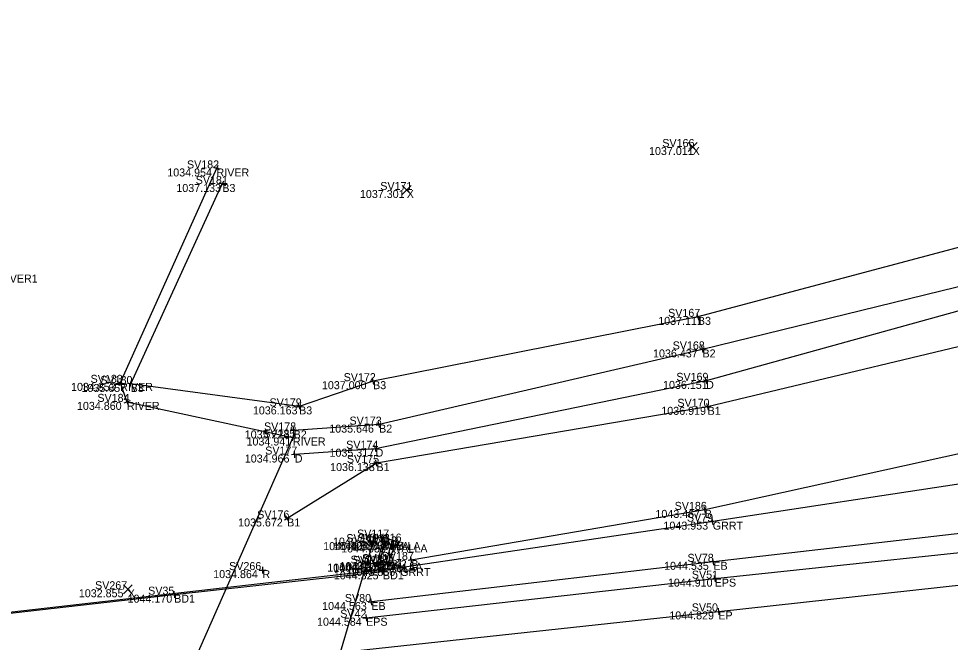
# Model space of a CAD drawing. Extents: x 1542529 to 1609210, y 587215 to 645373.
# Drawn here: x 1608930.2 to 1609069.9, y 645268.8 to 645362.2 of the extents above; entities that cross this region are included whole.
import ezdxf

# ---------------------------------------------------------------- set-up
doc = ezdxf.new("R2010")
doc.units = 0
for name, color, linetype in [('BR_X_SV_Abut', 7, 'Continuous'), ('BR_X_SV_Abut_Text', 7, 'Continuous'), ('BR_X_SV_Deck_Top', 7, 'Continuous'), ('BR_X_SV_Deck_Top_Text', 7, 'Continuous'), ('DR_X_Ditch', 7, 'Continuous'), ('HY_X_Water_Edge', 7, 'Continuous'), ('PV_X_EOP', 7, 'Continuous'), ('PV_X_Shoulder', 7, 'Continuous'), ('PV_X_Shoulder_Aggregate', 7, 'Continuous'), ('RD_X_GR_Rt', 7, 'Continuous'), ('SV_X_Break_Lines', 7, 'Continuous'), ('SV_X_Random_Point', 7, 'Continuous'), ('SV_X_Shot_Marker', 7, 'Continuous'), ('SV_X_Text_Comment', 7, 'Continuous'), ('SV_X_Text_Elevation', 7, 'Continuous'), ('SV_X_Text_Name', 7, 'Continuous'), ('SV_X_Toe_of_Slope', 7, 'Continuous'), ('SV_X_Top_of_Bank', 7, 'Continuous')]:
    doc.layers.add(name, color=color, linetype=linetype)

msp = doc.modelspace()

# ---------------------------------------------------------------- linework, layer by layer
at = {"layer": 'BR_X_SV_Abut'}
for points in [[(1608983.32, 645283.77), (1608967.84, 645231.45)], [(1608985.3, 645280.69), (1608986.07, 645283.42), (1608985.01, 645283.78), (1608984.29, 645280.5)]]:
    msp.add_lwpolyline(points, dxfattribs=at)
at = {"layer": 'BR_X_SV_Abut_Text'}
for p, q in [((1608983.8, 645283.63), (1608982.84, 645283.91)), ((1608983.46, 645284.25), (1608983.18, 645283.29)), ((1608983.32, 645283.77), (1608983.32, 645283.77)), ((1608985.48, 645283.61), (1608984.54, 645283.94)), ((1608984.85, 645283.3), (1608985.17, 645284.25)), ((1608985.01, 645283.78), (1608985.01, 645283.78)), ((1608985.93, 645282.93), (1608986.2, 645283.9)), ((1608985.58, 645283.55), (1608986.55, 645283.28)), ((1608986.07, 645283.42), (1608986.07, 645283.42)), ((1608984.4, 645280.99), (1608984.18, 645280.01)), ((1608984.82, 645280.82), (1608985.78, 645280.55)), ((1608985.17, 645280.21), (1608985.44, 645281.17)), ((1608984.78, 645280.39), (1608983.8, 645280.6)), ((1608984.29, 645280.5), (1608984.29, 645280.5)), ((1608985.3, 645280.69), (1608985.3, 645280.69))]:
    msp.add_line(p, q, dxfattribs=at)
at = {"layer": 'BR_X_SV_Deck_Top'}
msp.add_lwpolyline([(1608890.83, 645268.82), (1608915.28, 645271.59), (1608953.53, 645275.9), (1608984.83, 645279.39)], dxfattribs=at)
at = {"layer": 'BR_X_SV_Deck_Top_Text'}
for p, q in [((1608984.33, 645279.34), (1608985.32, 645279.45)), ((1608984.77, 645279.89), (1608984.88, 645278.9)), ((1608984.83, 645279.39), (1608984.83, 645279.39)), ((1608953.03, 645275.85), (1608954.02, 645275.96)), ((1608953.47, 645276.4), (1608953.58, 645275.4)), ((1608953.53, 645275.9), (1608953.53, 645275.9))]:
    msp.add_line(p, q, dxfattribs=at)
at = {"layer": 'DR_X_Ditch'}
msp.add_lwpolyline([(1609191.48, 645350.17), (1609137.17, 645337.41), (1609083.09, 645321.71), (1609033.27, 645307.94), (1608983.73, 645297.77), (1608971.61, 645296.9)], dxfattribs=at)
at = {"layer": 'HY_X_Water_Edge'}
msp.add_lwpolyline([(1608959.88, 645339.77), (1608945.44, 645307.64), (1608946.45, 645304.79), (1608971.33, 645299.45), (1608940.9, 645230.56)], dxfattribs=at)
at = {"layer": 'PV_X_EOP'}
msp.add_lwpolyline([(1608980.54, 645267.46), (1609035.11, 645273.39), (1609089.32, 645279.34), (1609143.54, 645285.01), (1609196.2, 645290.63)], dxfattribs=at)
at = {"layer": 'PV_X_Shoulder'}
msp.add_lwpolyline([(1608982.3, 645272.44), (1609034.56, 645278.3), (1609089.21, 645284.1), (1609142.99, 645289.57), (1609196.38, 645295.25)], dxfattribs=at)
at = {"layer": 'PV_X_Shoulder_Aggregate'}
msp.add_lwpolyline([(1609194.27, 645298.83), (1609142.65, 645292.29), (1609089.13, 645287.12), (1609034.36, 645280.82), (1608983.09, 645274.8)], dxfattribs=at)
at = {"layer": 'RD_X_GR_Rt'}
for p, q in [((1609087.09, 645294.87), (1609034.27, 645286.84)), ((1609034.27, 645286.84), (1608987.41, 645279.9)), ((1608987.41, 645279.9), (1608890.95, 645268.94))]:
    msp.add_line(p, q, dxfattribs=at)
at = {"layer": 'SV_X_Break_Lines'}
msp.add_lwpolyline([(1608985.67, 645280.77), (1608986.85, 645283.85), (1608984.91, 645284.45), (1608983.95, 645280.55)], dxfattribs=at)
at = {"layer": 'SV_X_Random_Point'}
for p, q in [((1609030.58, 645342.32), (1609031.91, 645343.65)), ((1609030.58, 645343.65), (1609031.91, 645342.32)), ((1608987.73, 645335.87), (1608989.07, 645337.21)), ((1608987.73, 645337.21), (1608989.07, 645335.87)), ((1608945.92, 645276.04), (1608947.25, 645277.37)), ((1608945.92, 645277.37), (1608947.25, 645276.04))]:
    msp.add_line(p, q, dxfattribs=at)
at = {"layer": 'SV_X_Shot_Marker'}
for p, q in [((1608960.34, 645339.56), (1608959.43, 645339.97)), ((1608960.09, 645340.23), (1608959.68, 645339.31)), ((1608959.88, 645339.77), (1608959.88, 645339.77)), ((1608960.3, 645337.64), (1608961.21, 645337.23)), ((1608960.54, 645336.98), (1608960.96, 645337.89)), ((1608960.75, 645337.44), (1608960.75, 645337.44)), ((1609032.52, 645317.66), (1609031.56, 645317.4)), ((1609032.17, 645317.05), (1609031.91, 645318.01)), ((1609032.04, 645317.53), (1609032.04, 645317.53)), ((1609032.85, 645312.17), (1609032.61, 645313.14)), ((1609033.22, 645312.77), (1609032.25, 645312.54)), ((1609032.73, 645312.65), (1609032.73, 645312.65)), ((1608945.9, 645307.44), (1608944.98, 645307.85)), ((1608945.64, 645308.1), (1608945.23, 645307.19)), ((1608945.44, 645307.64), (1608945.44, 645307.64)), ((1608947.5, 645307.4), (1608946.51, 645307.53)), ((1608946.94, 645306.97), (1608947.07, 645307.96)), ((1608947.01, 645307.47), (1608947.01, 645307.47)), ((1608983.84, 645307.99), (1608982.86, 645307.79)), ((1608983.45, 645307.4), (1608983.25, 645308.38)), ((1608983.35, 645307.89), (1608983.35, 645307.89)), ((1609033.76, 645308.08), (1609032.79, 645307.81)), ((1609033.41, 645307.46), (1609033.14, 645308.42)), ((1609033.27, 645307.94), (1609033.27, 645307.94)), ((1608946.92, 645304.96), (1608945.98, 645304.62)), ((1608946.28, 645305.26), (1608946.62, 645304.32)), ((1608946.45, 645304.79), (1608946.45, 645304.79)), ((1608972.42, 645303.64), (1608972.1, 645304.59)), ((1609033.61, 645303.56), (1609033.38, 645304.53)), ((1608972.73, 645304.27), (1608971.78, 645303.95)), ((1608972.26, 645304.11), (1608972.26, 645304.11)), ((1609033.98, 645304.16), (1609033.01, 645303.93)), ((1609033.5, 645304.05), (1609033.5, 645304.05)), ((1608984.36, 645300.89), (1608984.13, 645301.87)), ((1608971.93, 645300.54), (1608970.94, 645300.47)), ((1608971.47, 645300.01), (1608971.4, 645301.01)), ((1608971.44, 645300.51), (1608971.44, 645300.51)), ((1608984.73, 645301.49), (1608983.76, 645301.27)), ((1608984.25, 645301.38), (1608984.25, 645301.38)), ((1608970.84, 645299.55), (1608971.82, 645299.35)), ((1608971.43, 645299.94), (1608971.22, 645298.96)), ((1608971.33, 645299.45), (1608971.33, 645299.45)), ((1608984.22, 645297.87), (1608983.24, 645297.67)), ((1608983.83, 645297.28), (1608983.63, 645298.26)), ((1608983.73, 645297.77), (1608983.73, 645297.77)), ((1608972.1, 645296.93), (1608971.11, 645296.86)), ((1608971.64, 645296.4), (1608971.57, 645297.39)), ((1608971.61, 645296.9), (1608971.61, 645296.9)), ((1608984.34, 645295.7), (1608983.35, 645295.54)), ((1608983.93, 645295.13), (1608983.76, 645296.11)), ((1608983.85, 645295.62), (1608983.85, 645295.62)), ((1609033.57, 645288.71), (1609032.59, 645288.49)), ((1609033.19, 645288.11), (1609032.97, 645289.09)), ((1609033.08, 645288.6), (1609033.08, 645288.6)), ((1608970.9, 645287.58), (1608970.05, 645287.05)), ((1608970.74, 645286.89), (1608970.21, 645287.74)), ((1608970.47, 645287.32), (1608970.47, 645287.32)), ((1609034.76, 645286.92), (1609033.77, 645286.77)), ((1609034.34, 645286.35), (1609034.19, 645287.34)), ((1609034.27, 645286.84), (1609034.27, 645286.84)), ((1608985.39, 645284.3), (1608984.44, 645284.59)), ((1608984.77, 645283.97), (1608985.06, 645284.92)), ((1608984.91, 645284.45), (1608984.91, 645284.45)), ((1608986.38, 645284.03), (1608987.32, 645283.67)), ((1608986.67, 645283.38), (1608987.03, 645284.32)), ((1608986.85, 645283.85), (1608986.85, 645283.85)), ((1608984.07, 645281.04), (1608983.83, 645280.07)), ((1608985.2, 645280.95), (1608986.14, 645280.59)), ((1608985.49, 645280.3), (1608985.85, 645281.24)), ((1608989.58, 645281.17), (1608988.59, 645281)), ((1608989.17, 645280.6), (1608989, 645281.58)), ((1608989.08, 645281.09), (1608989.08, 645281.09)), ((1609034.85, 645280.88), (1609033.86, 645280.76)), ((1609034.41, 645280.32), (1609034.3, 645281.31)), ((1609034.36, 645280.82), (1609034.36, 645280.82)), ((1608966.26, 645279.58), (1608967.26, 645279.58)), ((1608966.76, 645280.08), (1608966.76, 645279.08)), ((1608966.76, 645279.58), (1608966.76, 645279.58)), ((1608984.44, 645280.43), (1608983.47, 645280.67)), ((1608983.95, 645280.55), (1608983.95, 645280.55)), ((1608985.67, 645280.77), (1608985.67, 645280.77)), ((1608987.9, 645279.95), (1608986.91, 645279.84)), ((1608987.46, 645279.4), (1608987.35, 645280.39)), ((1608987.41, 645279.9), (1608987.41, 645279.9)), ((1609034.06, 645278.24), (1609035.06, 645278.35)), ((1609034.5, 645278.79), (1609034.62, 645277.8)), ((1609034.56, 645278.3), (1609034.56, 645278.3)), ((1608983.15, 645274.31), (1608983.03, 645275.3)), ((1608983.59, 645274.86), (1608982.6, 645274.74)), ((1608983.09, 645274.8), (1608983.09, 645274.8)), ((1609035.06, 645273.89), (1609035.17, 645272.89)), ((1608981.8, 645272.38), (1608982.8, 645272.49)), ((1608982.24, 645272.93), (1608982.36, 645271.94)), ((1608982.3, 645272.44), (1608982.3, 645272.44)), ((1609034.61, 645273.33), (1609035.61, 645273.44)), ((1609035.11, 645273.39), (1609035.11, 645273.39))]:
    msp.add_line(p, q, dxfattribs=at)
at = {"layer": 'SV_X_Toe_of_Slope'}
for points in [[(1609191.16, 645354.4), (1609136.55, 645341.29), (1609082.76, 645324.9), (1609032.73, 645312.65), (1608984.25, 645301.38), (1608971.44, 645300.51)], [(1609191.65, 645347.51), (1609137.87, 645334.04), (1609084.02, 645316.13), (1609033.5, 645304.05), (1608983.85, 645295.62), (1608970.47, 645287.32)]]:
    msp.add_lwpolyline(points, dxfattribs=at)
at = {"layer": 'SV_X_Top_of_Bank'}
for points in [[(1609189.86, 645362.22), (1609135.71, 645347.66), (1609081.81, 645330.77), (1609032.04, 645317.53), (1608983.35, 645307.89), (1608972.26, 645304.11), (1608947.01, 645307.47), (1608960.75, 645337.44)], [(1609192.22, 645341.3), (1609141.43, 645321.19), (1609087.04, 645300.51), (1609033.08, 645288.6), (1608989.08, 645281.09)]]:
    msp.add_lwpolyline(points, dxfattribs=at)

# ---------------------------------------------------------------- texts
at = {"layer": 'BR_X_SV_Abut_Text'}
for s, p in [('SV119', (1608979.34, 645283.77)), ('SV113', (1608981.04, 645283.78)), ('1040.425', (1608975.87, 645282.57)), ('1044.030', (1608977.41, 645282.58)), ('SV112', (1608982.11, 645283.42)), ('WALLA', (1608983.32, 645282.57)), ('WALLA', (1608985.01, 645282.58)), ('1044.033', (1608978.57, 645282.22)), ('WALLA', (1608986.07, 645282.22)), ('SV114', (1608980.33, 645280.5)), ('SV111', (1608981.79, 645280.69)), ('1044.157', (1608977.4, 645279.3)), ('1044.152', (1608978.42, 645279.49)), ('WALLA', (1608984.29, 645279.3)), ('WALLA', (1608985.3, 645279.49))]:
    msp.add_text(s, height=1.2, dxfattribs=at).set_placement(p)
at = {"layer": 'BR_X_SV_Deck_Top_Text'}
for s, p in [('1044.325', (1608977.47, 645278.19)), ('SV41', (1608981.4, 645279.39)), ('BD1', (1608984.83, 645278.19)), ('SV35', (1608949.63, 645275.9)), ('1044.170', (1608946.55, 645274.7)), ('BD1', (1608953.53, 645274.7))]:
    msp.add_text(s, height=1.2, dxfattribs=at).set_placement(p)
at = {"layer": 'SV_X_Text_Comment'}
for s, p in [('X', (1609031.25, 645341.78)), ('RIVER', (1608959.88, 645338.57)), ('B3', (1608960.75, 645336.24)), ('X', (1608988.4, 645335.34)), ('RIVER1', (1608927.27, 645322.67)), ('B3', (1609032.04, 645316.33)), ('B2', (1609032.73, 645311.45)), ('RIVER', (1608945.44, 645306.44)), ('B3', (1608947.01, 645306.27)), ('B3', (1608983.35, 645306.69)), ('D', (1609033.27, 645306.74)), ('RIVER', (1608946.45, 645303.59)), ('B3', (1608972.26, 645302.91)), ('B1', (1609033.5, 645302.85)), ('B2', (1608971.44, 645299.31)), ('B2', (1608984.25, 645300.18)), ('RIVER', (1608971.33, 645298.25)), ('D', (1608983.73, 645296.57)), ('D', (1608971.61, 645295.7)), ('B1', (1608983.85, 645294.42)), ('B', (1609033.08, 645287.4)), ('B1', (1608970.47, 645286.12)), ('GRRT', (1609034.27, 645285.64)), ('B', (1608984.91, 645283.25)), ('B', (1608986.85, 645282.65)), ('B', (1608989.08, 645279.89)), ('EB', (1609034.36, 645279.62)), ('R', (1608966.76, 645278.38)), ('B', (1608983.95, 645279.35)), ('B', (1608985.67, 645279.57)), ('GRRT', (1608987.41, 645278.7)), ('EPS', (1609034.56, 645277.1)), ('X', (1608946.58, 645275.51)), ('EB', (1608983.09, 645273.6)), ('EPS', (1608982.3, 645271.24)), ('EP', (1609035.11, 645272.19))]:
    msp.add_text(s, height=1.2, dxfattribs=at).set_placement(p)
at = {"layer": 'SV_X_Text_Elevation'}
for s, p in [('1037.011', (1609024.72, 645341.78)), ('1034.954', (1608952.5, 645338.57)), ('1037.133', (1608953.86, 645336.24)), ('1037.301', (1608981.38, 645335.34)), ('1037.111', (1609026.1, 645316.33)), ('1036.437', (1609025.32, 645311.45)), ('1034.853', (1608938.07, 645306.44)), ('1035.657', (1608939.63, 645306.27)), ('1037.000', (1608975.68, 645306.69)), ('1036.151', (1609026.82, 645306.74)), ('1034.860', (1608938.96, 645303.59)), ('1036.163', (1608965.33, 645302.91)), ('1036.919', (1609026.56, 645302.85)), ('1035.223', (1608964.11, 645299.31)), ('1035.646', (1608976.78, 645300.18)), ('1034.941', (1608964.38, 645298.25)), ('1035.317', (1608976.82, 645296.57)), ('1034.966', (1608964.12, 645295.7)), ('1036.138', (1608976.91, 645294.42)), ('1043.467', (1609025.68, 645287.4)), ('1035.672', (1608963.12, 645286.12)), ('1043.953', (1609026.88, 645285.64)), ('1040.636', (1608977.34, 645283.25)), ('1041.374', (1608979.98, 645282.65)), ('1043.377', (1608978.3, 645279.57)), ('1043.442', (1608981.7, 645279.89)), ('1044.535', (1609026.98, 645279.62)), ('1034.864', (1608959.38, 645278.38)), ('1040.453', (1608976.48, 645279.35)), ('1043.856', (1608979.96, 645278.7)), ('1044.910', (1609027.55, 645277.1)), ('1032.855', (1608939.24, 645275.51)), ('1044.563', (1608975.71, 645273.6)), ('1044.584', (1608974.95, 645271.24)), ('1044.829', (1609027.76, 645272.19))]:
    msp.add_text(s, height=1.2, dxfattribs=at).set_placement(p)
at = {"layer": 'SV_X_Text_Name'}
for s, p in [('SV166', (1609026.71, 645342.98)), ('SV182', (1608955.45, 645339.77)), ('SV181', (1608956.76, 645337.44)), ('SV171', (1608984.43, 645336.54)), ('SV167', (1609027.58, 645317.53)), ('SV168', (1609028.26, 645312.65)), ('SV183', (1608941, 645307.64)), ('SV172', (1608978.94, 645307.89)), ('SV169', (1609028.81, 645307.94)), ('SV180', (1608942.46, 645307.47)), ('SV184', (1608942.02, 645304.79)), ('SV179', (1608967.83, 645304.11)), ('SV170', (1609028.97, 645304.05)), ('SV173', (1608979.82, 645301.38)), ('SV185', (1608966.89, 645299.45)), ('SV178', (1608967, 645300.51)), ('SV174', (1608979.32, 645297.77)), ('SV177', (1608967.18, 645296.9)), ('SV175', (1608979.43, 645295.62)), ('SV186', (1609028.56, 645288.6)), ('SV176', (1608965.98, 645287.32)), ('SV79', (1609030.4, 645286.84)), ('SV117', (1608980.95, 645284.45)), ('SV116', (1608982.81, 645283.85)), ('SV187', (1608984.64, 645281.09)), ('SV266', (1608961.77, 645279.58)), ('SV118', (1608979.98, 645280.55)), ('SV115', (1608981.7, 645280.77)), ('SV81', (1608983.98, 645279.9)), ('SV78', (1609030.49, 645280.82)), ('SV51', (1609031.14, 645278.3)), ('SV267', (1608941.67, 645276.71)), ('SV80', (1608979.12, 645274.8)), ('SV50', (1609031.13, 645273.39)), ('SV42', (1608978.43, 645272.44))]:
    msp.add_text(s, height=1.2, dxfattribs=at).set_placement(p)

doc.saveas('drawing.dxf')
